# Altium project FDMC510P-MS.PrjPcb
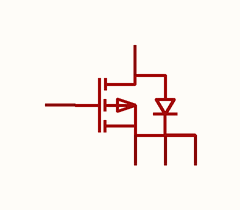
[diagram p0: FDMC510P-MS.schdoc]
1 sheet, 1 parts. Net scope: global (net labels, ports and power ports of the same name join across sheets).

## Sheet FDMC510P-MS.schdoc
size 127 x 101 mm

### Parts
Q?  fdmc510p-ms  [POWERDI3333-8_DMN7022LFGQ-7]  (value not drawn)

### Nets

Not connected (* = marked no-connect by the designer): Q? 1(S) 2(S) 3(S) 4(G) 5(D)

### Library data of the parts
Q? = fdmc510p-ms: 数量:1个P沟道;漏源电压(Vdss):20V;连续漏极电流(Id):60A;导通电阻(RDS(on)):12mΩ@2.5V;耗散功率(Pd):22W;阈值电压(Vgs(th)):1V;; Manufacturer: MSKSEMI(美森科); AddInBom: yes; ModelId: 296e462280334ba794f41fc0f4558c2c; ModelTransform: 130.708,130.708,0,0,0,0,0,18.625,0; Number: 1个P沟道; Drain to Source Voltage: 20V; Current - Continuous Drain(Id): 60A; Pd - Power Dissipation: 22W; Gate Threshold Voltage (Vgs(th)): 1V; Gate Charge(Qg): 35nC@4.5V; Input Capacitance(Ciss): 2.8nF; Type: P沟道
